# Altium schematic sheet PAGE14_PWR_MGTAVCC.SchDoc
size 381 x 381 mm; SheetNumber: 15; SheetTotal: 28
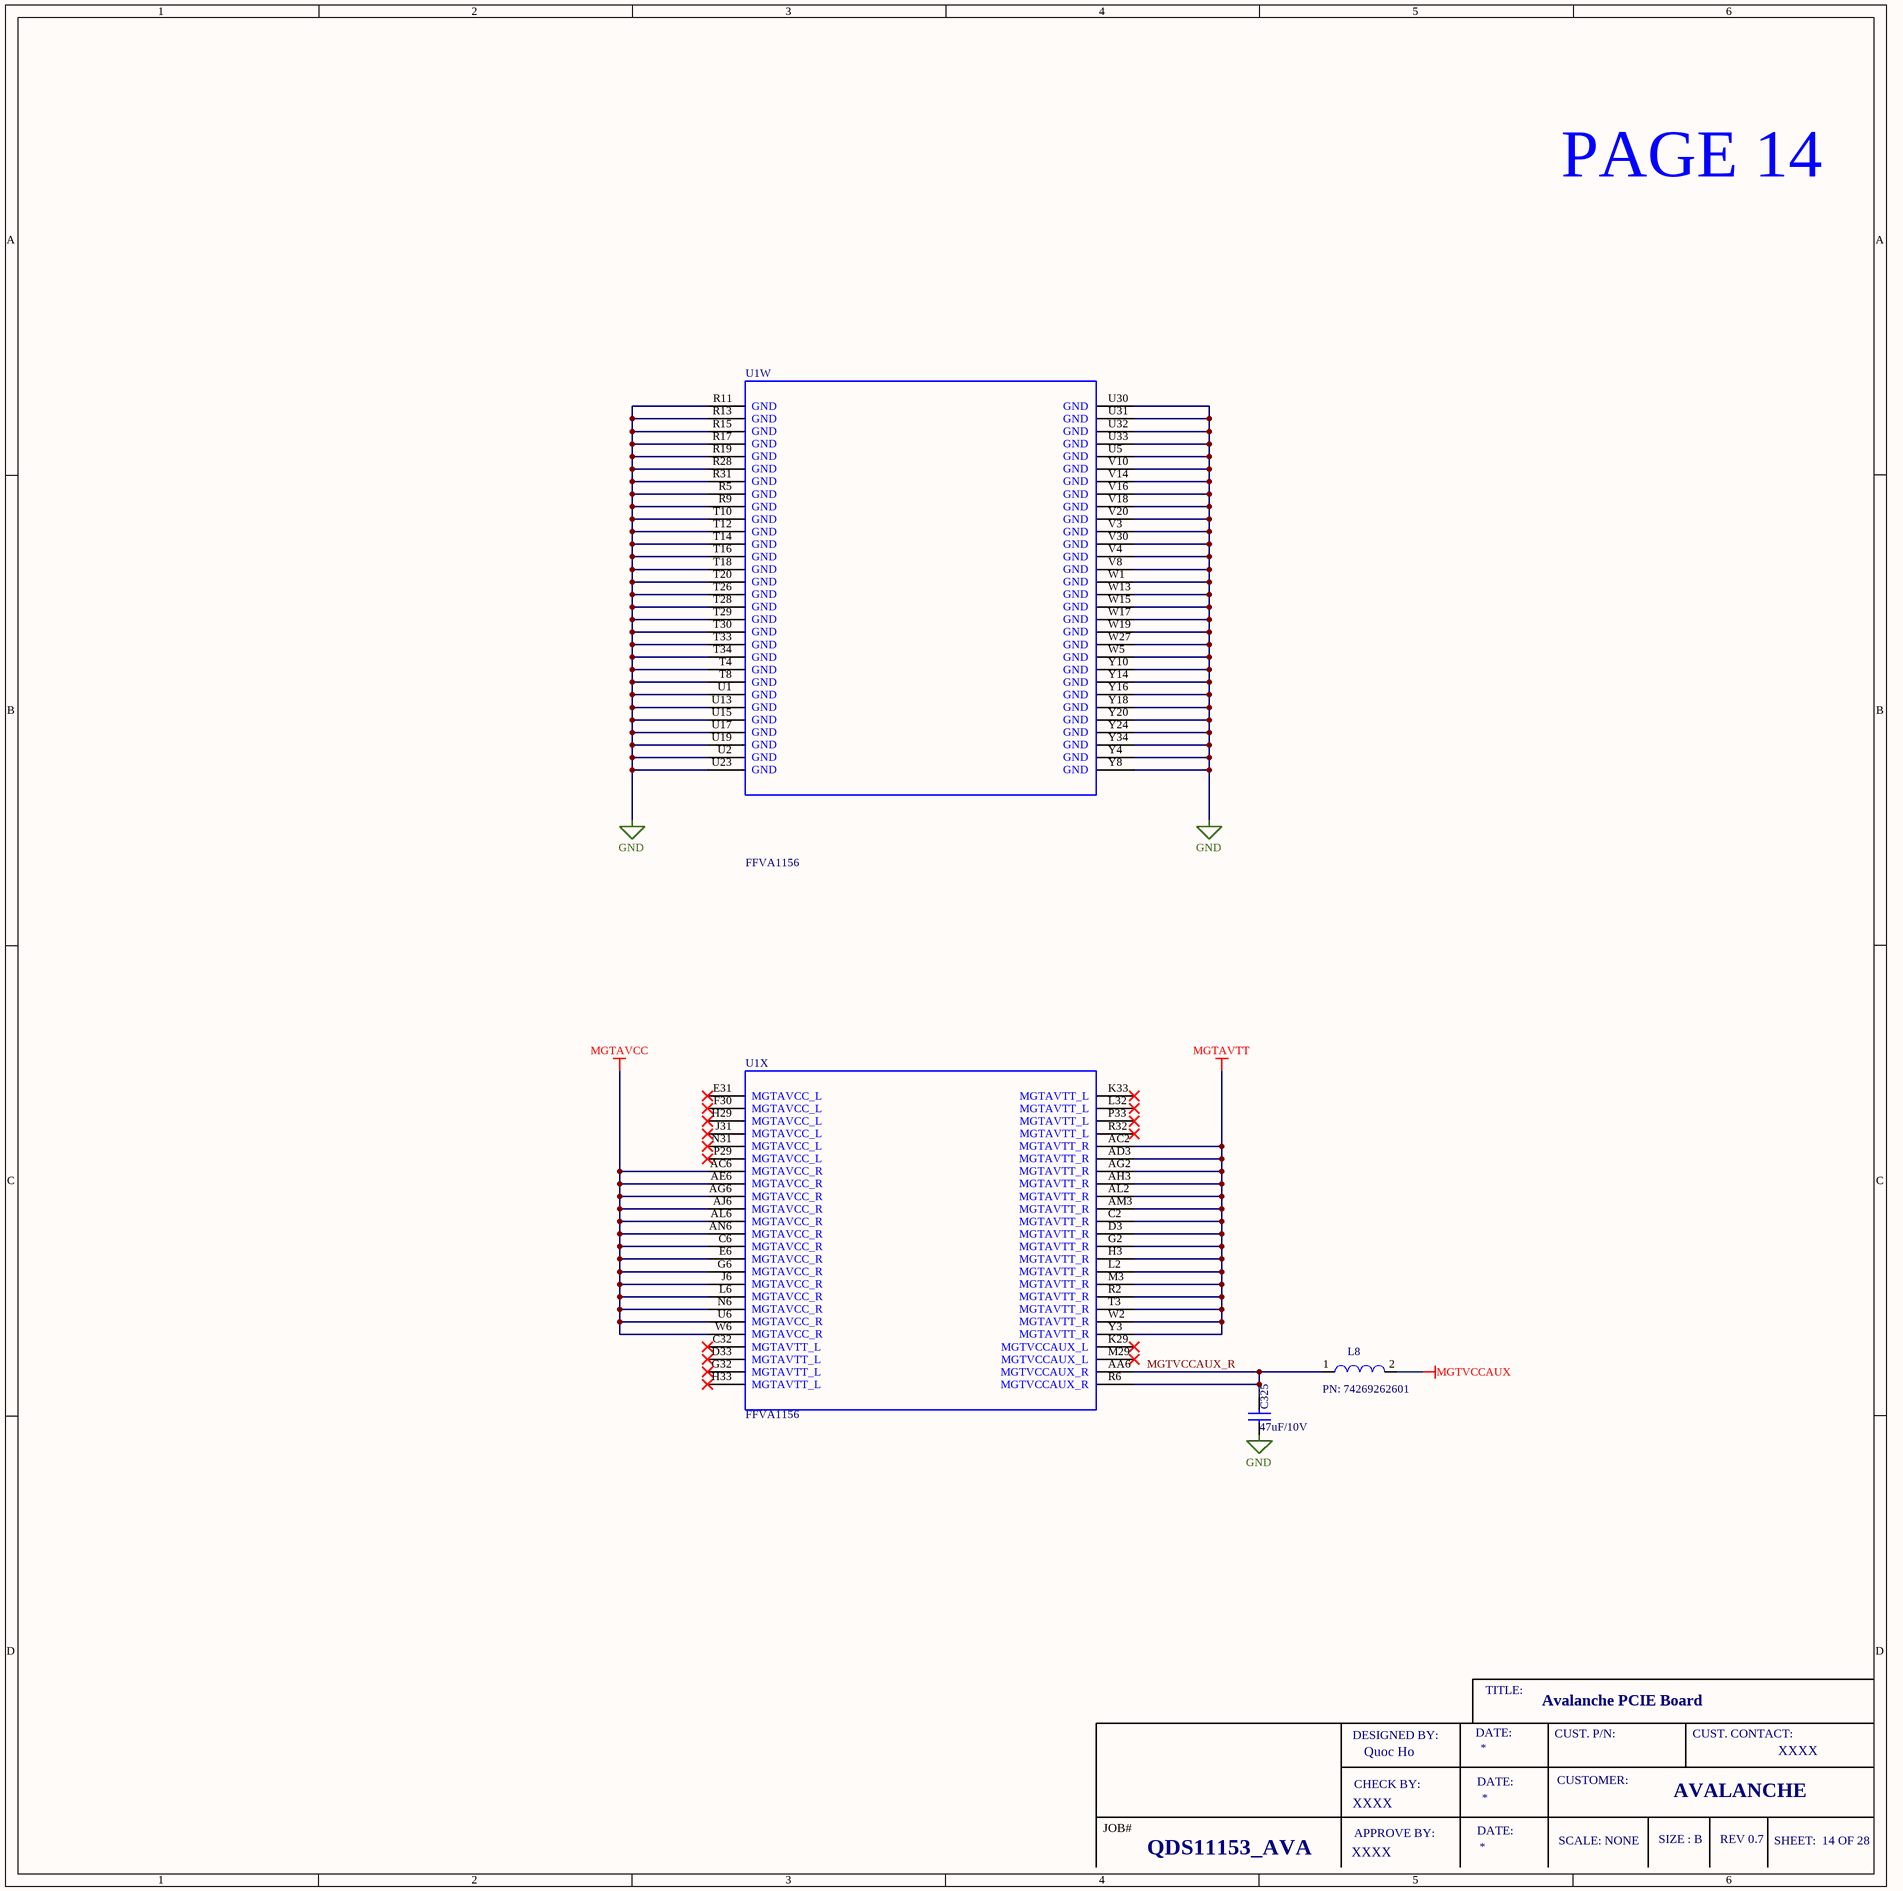
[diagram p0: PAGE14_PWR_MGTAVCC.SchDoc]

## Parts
C325  47uF/10V  [CN_0805]
L8  PN: 74269262601  [74269262601]
U1  FFVA1156  [FFVA1156]  (parts W,X of 25)

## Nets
GND: C325.1 U1.R5(GND) U1.R9(GND) U1.R11(GND) U1.R13(GND) U1.R15(GND) U1.R17(GND) U1.R19(GND) U1.R28(GND) U1.R31(GND) U1.T4(GND) U1.T8(GND) U1.T10(GND) U1.T12(GND) U1.T14(GND) U1.T16(GND) U1.T18(GND) U1.T20(GND) U1.T26(GND) U1.T28(GND) U1.T29(GND) U1.T30(GND) U1.T33(GND) U1.T34(GND) U1.U1(GND) U1.U2(GND) U1.U5(GND) U1.U13(GND) U1.U15(GND) U1.U17(GND) U1.U19(GND) U1.U23(GND) U1.U30(GND) U1.U31(GND) U1.U32(GND) U1.U33(GND) U1.V3(GND) U1.V4(GND) U1.V8(GND) U1.V10(GND) U1.V14(GND) U1.V16(GND) U1.V18(GND) U1.V20(GND) U1.V30(GND) U1.W1(GND) U1.W5(GND) U1.W13(GND) U1.W15(GND) U1.W17(GND) U1.W19(GND) U1.W27(GND) U1.Y4(GND) U1.Y8(GND) U1.Y10(GND) U1.Y14(GND) U1.Y16(GND) U1.Y18(GND) U1.Y20(GND) U1.Y24(GND) U1.Y34(GND)
MGTAVCC: U1.AC6(MGTAVCC_R) U1.AE6(MGTAVCC_R) U1.AG6(MGTAVCC_R) U1.AJ6(MGTAVCC_R) U1.AL6(MGTAVCC_R) U1.AN6(MGTAVCC_R) U1.C6(MGTAVCC_R) U1.E6(MGTAVCC_R) U1.G6(MGTAVCC_R) U1.J6(MGTAVCC_R) U1.L6(MGTAVCC_R) U1.N6(MGTAVCC_R) U1.U6(MGTAVCC_R) U1.W6(MGTAVCC_R)
MGTAVTT: U1.AC2(MGTAVTT_R) U1.AD3(MGTAVTT_R) U1.AG2(MGTAVTT_R) U1.AH3(MGTAVTT_R) U1.AL2(MGTAVTT_R) U1.AM3(MGTAVTT_R) U1.C2(MGTAVTT_R) U1.D3(MGTAVTT_R) U1.G2(MGTAVTT_R) U1.H3(MGTAVTT_R) U1.L2(MGTAVTT_R) U1.M3(MGTAVTT_R) U1.R2(MGTAVTT_R) U1.T3(MGTAVTT_R) U1.W2(MGTAVTT_R) U1.Y3(MGTAVTT_R)
MGTVCCAUX: L8.2
MGTVCCAUX_R: C325.2 L8.1 U1.AA6(MGTVCCAUX_R) U1.R6(MGTVCCAUX_R)

Not connected (* = marked no-connect by the designer): U1 C32(MGTAVTT_L)* D33(MGTAVTT_L)* E31(MGTAVCC_L)* F30(MGTAVCC_L)* G32(MGTAVTT_L)* H29(MGTAVCC_L)* H33(MGTAVTT_L)* J31(MGTAVCC_L)* K29(MGTVCCAUX_L)* K33(MGTAVTT_L)* L32(MGTAVTT_L)* M29(MGTVCCAUX_L)* N31(MGTAVCC_L)* P29(MGTAVCC_L)* P33(MGTAVTT_L)* R32(MGTAVTT_L)*

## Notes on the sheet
- PAGE 14
- TITLE:
- Avalanche PCIE Board
- DESIGNED BY:
- CHECK BY:
- Quoc Ho
- DATE:
- CUST. P/N:
- CUSTOMER:
- CUST. CONTACT:
- XXXX
- JOB#
- APPROVE BY:
- SCALE: NONE
- SIZE : B
- AVALANCHE
- REV 0.7
- SHEET:  14 OF 28
- QDS11153_AVA

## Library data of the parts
C325 = CAP: CAP CER 47UF 10V X5R 0805; Manufacturer Part Number: GRM21BR61A476ME15K; Manufacturer: Murata Electronics
L8 = INDUCTOR: WE-TMSB SMT EMI SUPPRESSION FERR; Manufacturer: Würth Elektronik
U1 = FFVA1156: IC FPGA 516 I/O 1156FCBGA; Manufacturer Part Number: XCKU15P-1FFVA1156E; Manufacturer: AMD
